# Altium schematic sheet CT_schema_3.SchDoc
size 316 x 185 mm
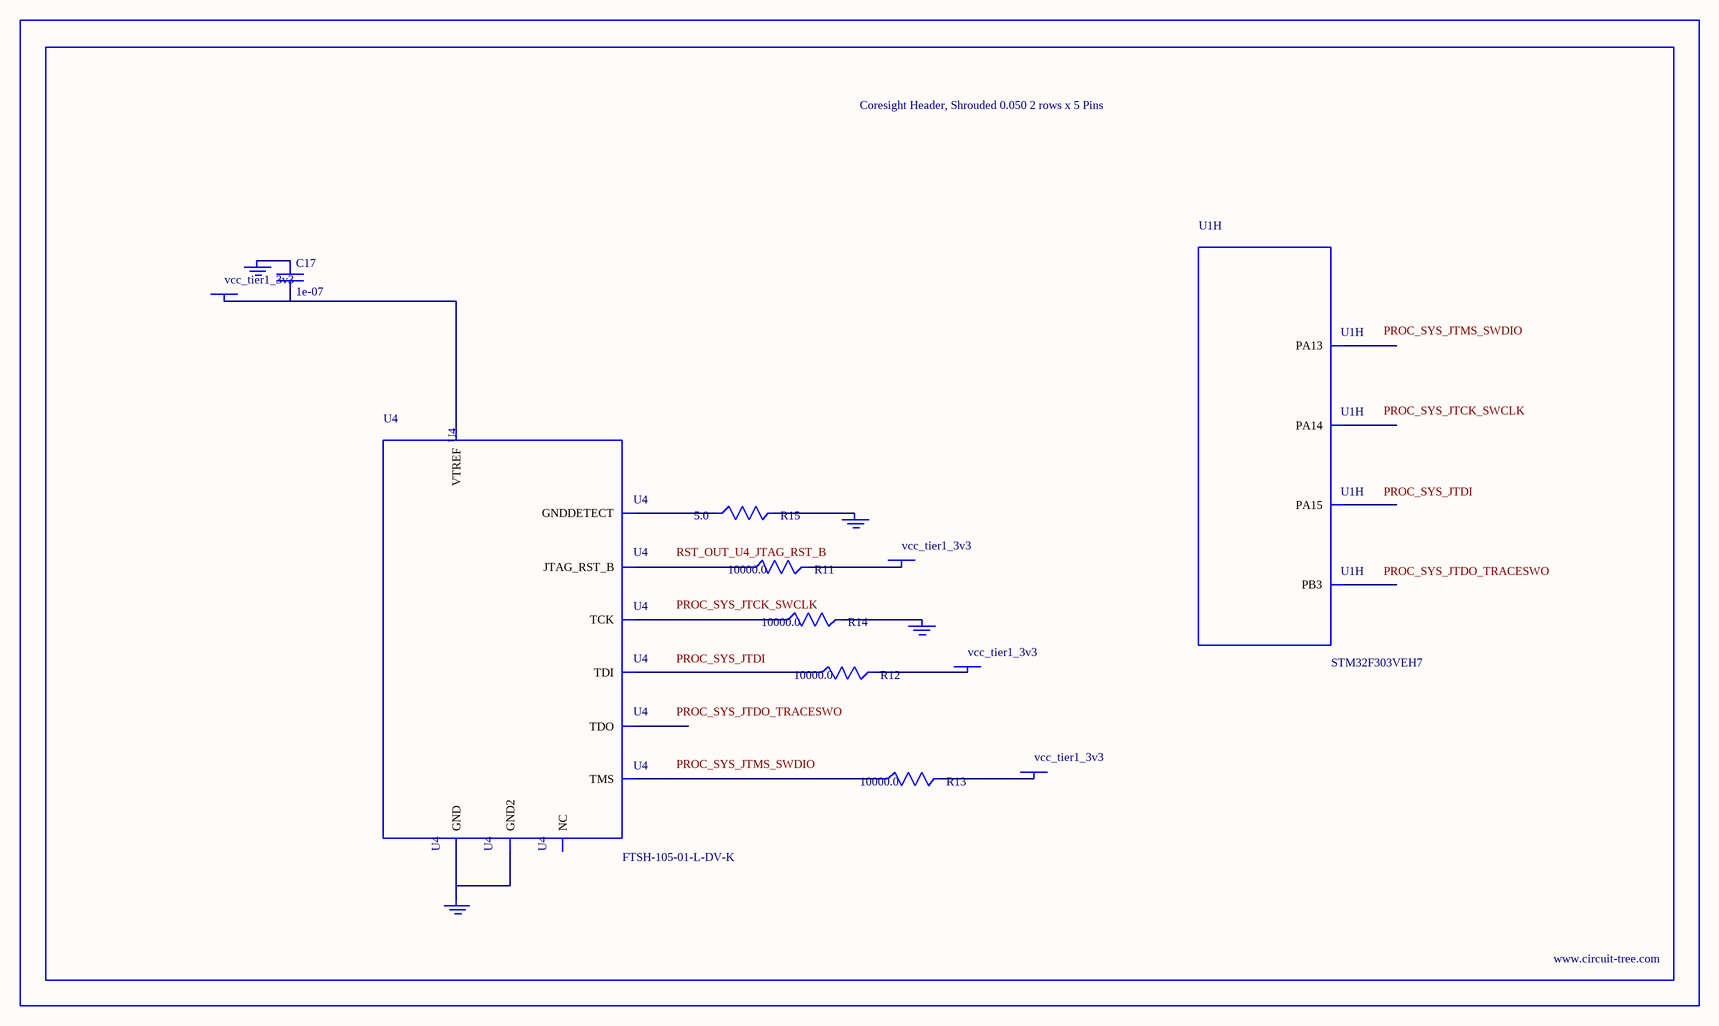
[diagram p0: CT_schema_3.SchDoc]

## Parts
BORDER2  (no value)
C17  1e-07  [C0402]
GND_INSTANCE_2_0  (no value)
GND_INSTANCE_2_1  (no value)
GND_INSTANCE_2_2  (no value)
GND_INSTANCE_2_3  (no value)
POWER_INSTANCE_2_0  vcc_tier1_3v3
POWER_INSTANCE_2_1  vcc_tier1_3v3
POWER_INSTANCE_2_2  vcc_tier1_3v3
POWER_INSTANCE_2_3  vcc_tier1_3v3
R11  10000.0  [R0603]
R12  10000.0  [R0603]
R13  10000.0  [R0603]
R14  10000.0  [R0603]
R15  5.0  [R0603]
U1  STM32F303VEH7  [UFBGA100]  (part H of 10)
U4  FTSH-105-01-L-DV-K  [SAMTEC_FTSH-105-01-L-DV-K]

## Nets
NetC17_1: C17.1 GND_INSTANCE_2_0.0(GND)
NetC17_2: C17.2 POWER_INSTANCE_2_0.0(PWR) U4.1(VTREF)
NetGND_INSTANCE_2_1_0: GND_INSTANCE_2_1.0(GND) R14.2
NetGND_INSTANCE_2_2_0: GND_INSTANCE_2_2.0(GND) R15.2
NetGND_INSTANCE_2_3_0: GND_INSTANCE_2_3.0(GND) U4.3(GND) U4.5(GND2)
NetPOWER_INSTANCE_2_1_0: POWER_INSTANCE_2_1.0(PWR) R13.2
NetPOWER_INSTANCE_2_2_0: POWER_INSTANCE_2_2.0(PWR) R12.2
NetPOWER_INSTANCE_2_3_0: POWER_INSTANCE_2_3.0(PWR) R11.2
NetR11_1: R11.1 U4.10(JTAG_RST_B)
NetR12_1: R12.1 U4.8(TDI)
NetR13_1: R13.1 U4.2(TMS)
NetR14_1: R14.1 U4.4(TCK)
NetR15_1: R15.1 U4.9(GNDDETECT)

Not connected (* = marked no-connect by the designer): U1 A8(PB3) A9(PA15) A10(PA14) A11(PA13); U4 6(TDO) 7(NC)

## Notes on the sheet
- Labels drawn without touching a wire or pin: PROC_SYS_JTCK_SWCLK, PROC_SYS_JTDI, PROC_SYS_JTDO_TRACESWO, PROC_SYS_JTMS_SWDIO, RST_OUT_U4_JTAG_RST_B

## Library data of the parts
BORDER2 = BORDER_PAGE2
C17 = C0402C104K3RACTU
GND_INSTANCE_2_0-GND_INSTANCE_2_3 = GND
POWER_INSTANCE_2_0-POWER_INSTANCE_2_3 = PWR
R11-R14 = RC0603JR-0710KL
R15 = ERJ-3GEYJ5R1V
